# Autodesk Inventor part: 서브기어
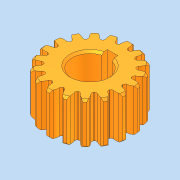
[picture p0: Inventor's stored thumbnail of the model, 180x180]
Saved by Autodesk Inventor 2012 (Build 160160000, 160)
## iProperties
Company: 한국ATC센터
Created: 2014-12
Part Number: 서브기어
Document SubType Name: Modeling
Designer: KYOUNG IL JANG
Density: 1 g/cm^3
Mass: 15.166 g
Surface Area: 69.6172 cm^2
Volume: 15.166 cm^3
Material: 기본값
Author: KYOUNG IL JANG
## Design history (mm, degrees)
sketch "스케치1"
  geometry: C1 r 15.5 at (0, 0); A1 r 1.155 centre (-2.906, 16.386) between (-2.542, 15.29) and (-1.751, 16.378); A2 r 5.602 centre (3.849, 16.522) between (-1.326, 18.666) and (-1.751, 16.378); A3 r 9.354 centre (7.378, 15.24) between (-0.682, 19.988) and (-1.326, 18.666); A4 r 1.155 centre (2.906, 16.386) between (1.751, 16.378) and (2.542, 15.29); A5 r 5.602 centre (-3.849, 16.522) between (1.751, 16.378) and (1.326, 18.666); A6 r 9.354 centre (-7.378, 15.24) between (1.326, 18.666) and (0.682, 19.988); A7 r 20 centre (0, 0) between (0.682, 19.988) and (-0.682, 19.988); A8 r 15.5 centre (0, 0) between (2.542, 15.29) and (-2.542, 15.29); 1 further point
  constraints: 16 point on circle, 9 centre point, 2 coincident
extrude "돌출1" new body sketch "스케치1" stored distance "d0" = 20; taper "d1" = 0 deg
extrude "돌출2" join sketch "스케치1" stored distance "d2" = 20; taper "d3" = 0 deg
chamfer "모따기1" distance "d4" = 1; stored, may be unused: second distance "d5" = 2, angle "d6" = 45 deg
hole "구멍1" diameter "d12" = 17; stored, may be unused: countersink angle "d16" = 90 deg, drill point angle "d18" = 118 deg; dims "d10" = 10, "d11" = 10, "d13" = 6, "d14" = 4, "d15" = 2, "d17" = 8
sketch "스케치2"
  geometry: L1 (-2.5, 8.124)-(-2.5, 10.8); L2 (-2.5, 10.8)-(2.5, 10.8); L3 (2.5, 10.8)-(2.5, 8.124); A1 r 8.5 centre (0, 0) between (-2.5, 8.124) and (2.5, 8.124) reference; 1 further point
  constraints: 6 end point, 2 parallel, 2 point on circle, 1 horizontal, 1 vertical
  dimensions: "d22" = 5 distance of L1.end L2.end; "d23" = 2.3 distance edge to line of A1 L2
extrude "돌출3" cut sketch "스케치2" stored distance "d24" = 20; taper "d25" = 0 deg
chamfer "모따기2" distance "d19" = 1; stored, may be unused: second distance "d20" = 2, angle "d21" = 45 deg
node "솔리드1"
pattern_circular "원형 패턴1" dims angle "d8" = 360 deg
